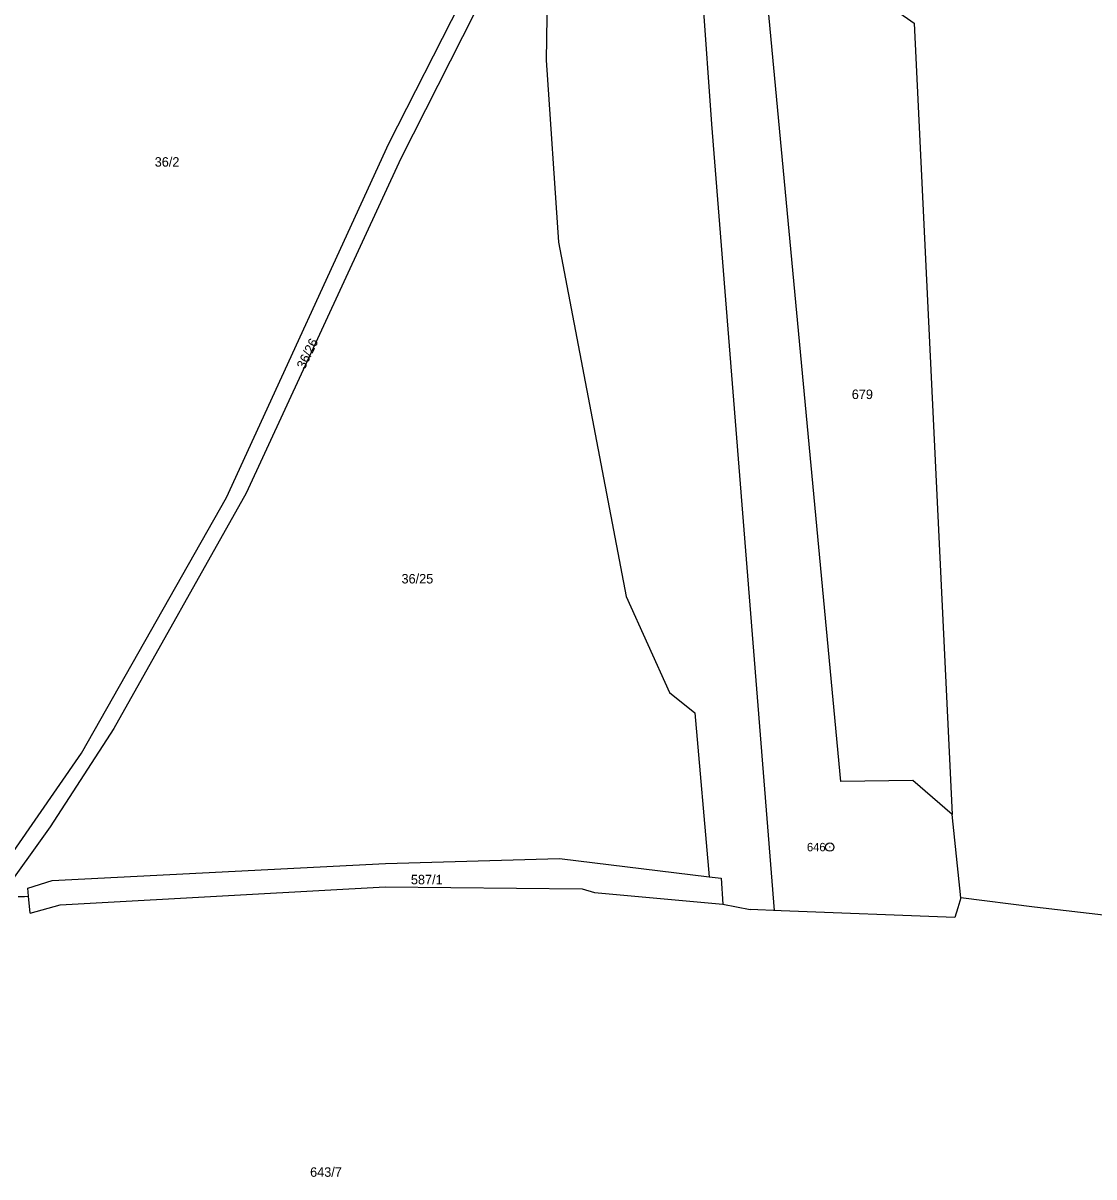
# Model space of a CAD drawing. Extents: x -783948 to -781889, y -1005870 to -1004430.
# Drawn here: x -782454.1 to -782262.2, y -1005868.7 to -1005661.9 of the extents above; entities that cross this region are included whole.
import ezdxf

# ---------------------------------------------------------------- set-up
doc = ezdxf.new("R2010")
doc.units = 0
for name, color, linetype in [('Vrstva 1', 7, 'Continuous'), ('Vrstva 2', 7, 'Continuous'), ('Vrstva 6', 7, 'Continuous'), ('Vrstva 8', 7, 'Continuous')]:
    doc.layers.add(name, color=color, linetype=linetype)

msp = doc.modelspace()

# ---------------------------------------------------------------- linework, layer by layer
at = {"layer": 'Vrstva 1'}
for p, q in [((-782286.06, -1005818.72), (-782287.6, -1005803.77)), ((-782357.99, -1005811.67), (-782331.2, -1005814.93)), ((-782331.2, -1005814.93), (-782329.02, -1005815.19)), ((-782329.02, -1005815.19), (-782328.75, -1005819.83)), ((-782453.15, -1005818.39), (-782453.28, -1005816.98)), ((-782452.85, -1005821.47), (-782453.15, -1005818.39)), ((-782452.85, -1005821.47), (-782447.52, -1005819.93)), ((-782328.75, -1005819.83), (-782323.82, -1005820.82)), ((-782286.59, -1005820.47), (-782287.18, -1005822.22)), ((-782286.06, -1005818.72), (-782286.59, -1005820.47)), ((-782272.9, -1005820.4), (-782286.06, -1005818.72)), ((-782318.25, -1005821.03), (-782323.82, -1005820.82)), ((-782287.18, -1005822.22), (-782318.25, -1005821.03))]:
    msp.add_line(p, q, dxfattribs=at)
for points in [[(-782459.82, -1005815.99), (-782443.68, -1005792.79), (-782417.66, -1005746.96), (-782388.6, -1005683.51), (-782362.9, -1005633.05), (-782362.27, -1005590.2)], [(-782359.84, -1005633.71), (-782386.44, -1005686.23), (-782414.15, -1005746.16), (-782437.86, -1005788.34), (-782449.27, -1005805.98), (-782458.16, -1005818.32)], [(-782359.84, -1005633.71), (-782360.42, -1005668.62), (-782358.18, -1005701.23), (-782346.04, -1005764.72), (-782338.28, -1005781.93), (-782333.75, -1005785.53), (-782331.2, -1005814.93)], [(-782287.6, -1005803.77), (-782294.69, -1005797.67), (-782307.56, -1005797.88), (-782322.17, -1005642.53)], [(-782322.17, -1005642.53), (-782294.44, -1005661.97), (-782287.6, -1005803.77)], [(-782453.28, -1005816.98), (-782448.93, -1005815.58), (-782389.16, -1005812.57), (-782357.99, -1005811.67)], [(-782455.01, -1005818.44), (-782453.88, -1005818.48), (-782453.15, -1005818.39)], [(-782447.52, -1005819.93), (-782414.09, -1005818.09), (-782389.25, -1005816.72), (-782353.97, -1005817.11)], [(-782353.97, -1005817.11), (-782351.72, -1005817.72), (-782328.75, -1005819.83)], [(-782167.71, -1005833.14), (-782240.92, -1005824.05), (-782272.9, -1005820.4)]]:
    msp.add_lwpolyline(points, dxfattribs=at)
at = {"layer": 'Vrstva 6'}
for p, q in [((-782338.68, -1005567.1), (-782330.78, -1005680.08)), ((-782330.78, -1005680.08), (-782319.53, -1005820.98))]:
    msp.add_line(p, q, dxfattribs=at)
at = {"layer": 'Vrstva 8'}
for radius in [0.75, 0.03]:
    msp.add_circle((-782309.56, -1005809.61), radius, dxfattribs=at)

# ---------------------------------------------------------------- texts
at = {"layer": 'Vrstva 2'}
for s, p in [('36/2', (-782430.55, -1005687.68)), ('679', (-782305.62, -1005729.32)), ('36/25', (-782386.32, -1005762.37)), ('587/1', (-782384.64, -1005816.28)), ('643/7', (-782402.7, -1005868.69))]:
    msp.add_text(s, height=1.7, dxfattribs=at).set_placement(p)
msp.add_text('36/26', height=1.7, rotation=64, dxfattribs=at).set_placement((-782403.68, -1005724.11))
at = {"layer": 'Vrstva 8'}
msp.add_text('646', height=1.5, dxfattribs=at).set_placement((-782313.66, -1005810.36))

doc.saveas('drawing.dxf')
